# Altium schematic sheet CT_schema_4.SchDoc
size 310 x 177 mm
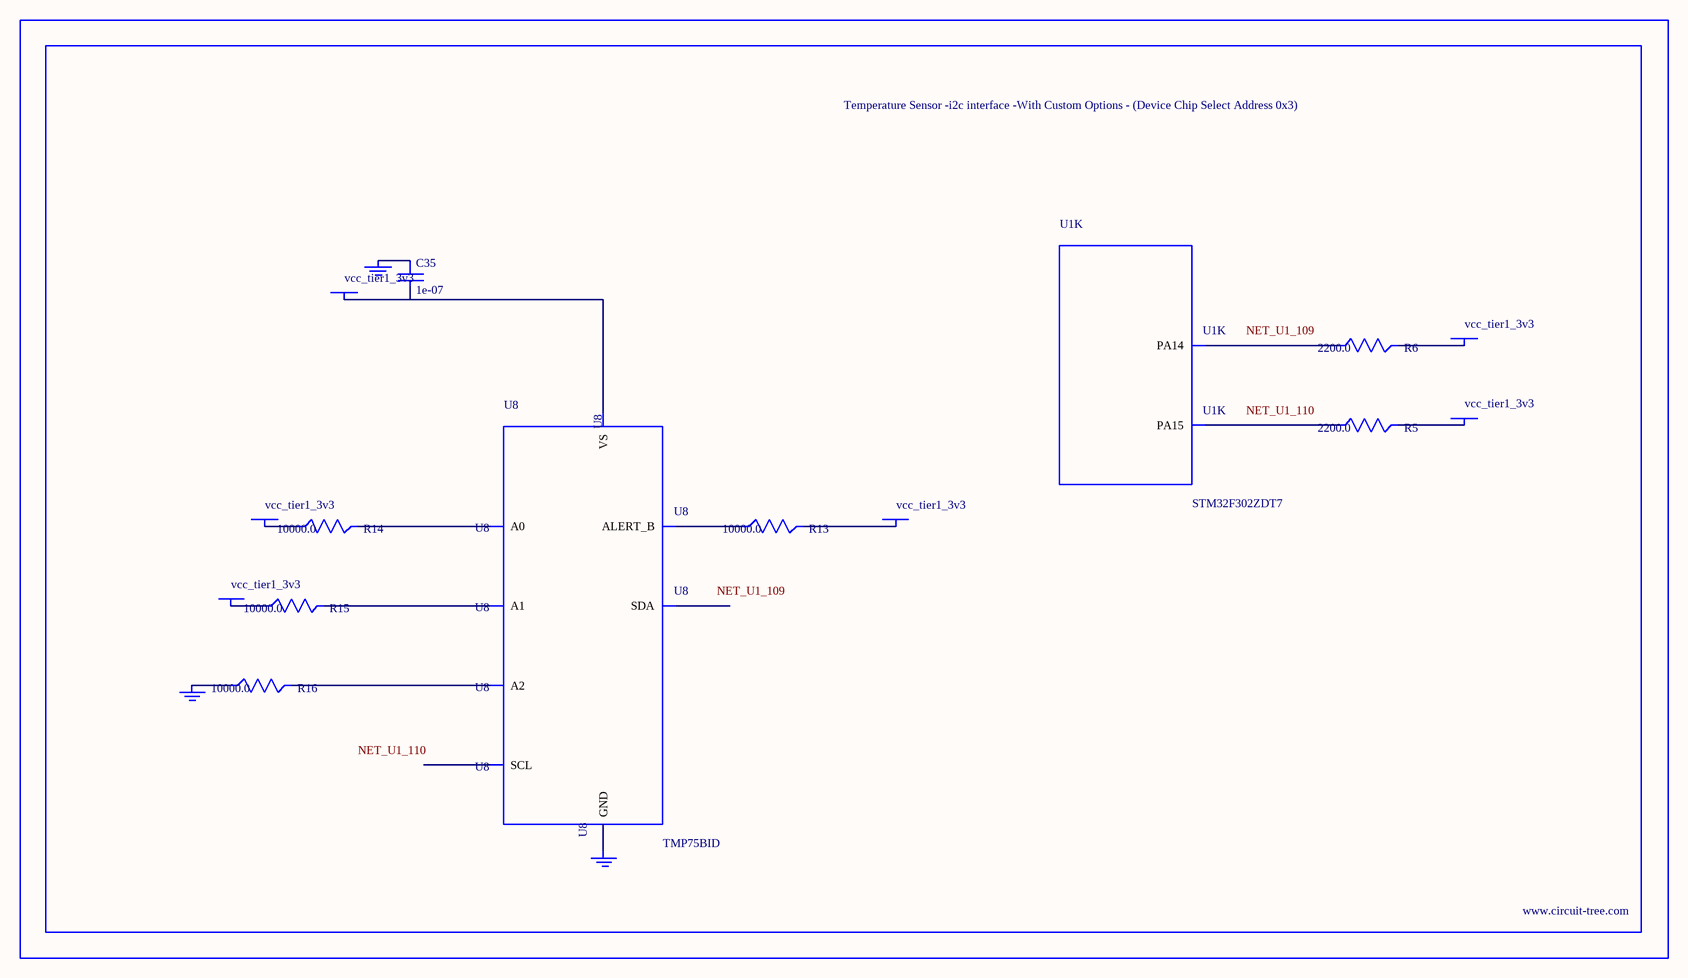
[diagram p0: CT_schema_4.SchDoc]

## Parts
BORDER3  (no value)
C35  1e-07  [C0402]
GND_INSTANCE_3_0  (no value)
GND_INSTANCE_3_1  (no value)
GND_INSTANCE_3_2  (no value)
POWER_INSTANCE_3_0  vcc_tier1_3v3
POWER_INSTANCE_3_1  vcc_tier1_3v3
POWER_INSTANCE_3_2  vcc_tier1_3v3
POWER_INSTANCE_3_3  vcc_tier1_3v3
POWER_INSTANCE_3_4  vcc_tier1_3v3
POWER_INSTANCE_3_5  vcc_tier1_3v3
R5  2200.0  [R0603]
R6  2200.0  [R0603]
R13  10000.0  [R0603]
R14  10000.0  [R0603]
R15  10000.0  [R0603]
R16  10000.0  [R0603]
U1  STM32F302ZDT7  [LQFP144]  (part K of 12)
U8  TMP75BID  [SOIC-8]

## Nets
NetC35_1: C35.1 GND_INSTANCE_3_1.0(GND)
NetC35_2: C35.2 POWER_INSTANCE_3_3.0(PWR) U8.8(VS)
NetGND_INSTANCE_3_0_0: GND_INSTANCE_3_0.0(GND) R16.1
NetGND_INSTANCE_3_2_0: GND_INSTANCE_3_2.0(GND) U8.4(GND)
NetPOWER_INSTANCE_3_0_0: POWER_INSTANCE_3_0.0(PWR) R13.2
NetPOWER_INSTANCE_3_1_0: POWER_INSTANCE_3_1.0(PWR) R15.1
NetPOWER_INSTANCE_3_2_0: POWER_INSTANCE_3_2.0(PWR) R14.1
NetPOWER_INSTANCE_3_4_0: POWER_INSTANCE_3_4.0(PWR) R6.2
NetPOWER_INSTANCE_3_5_0: POWER_INSTANCE_3_5.0(PWR) R5.2
NetR5_1: R5.1 U1.110(PA15)
NetR6_1: R6.1 U1.109(PA14)
NetR13_1: R13.1 U8.3(ALERT_B)
NetR14_2: R14.2 U8.7(A0)
NetR15_2: R15.2 U8.6(A1)
NetR16_2: R16.2 U8.5(A2)

Not connected (* = marked no-connect by the designer): U8 1(SDA) 2(SCL)

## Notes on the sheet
- Labels drawn without touching a wire or pin: NET_U1_109, NET_U1_110

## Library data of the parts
BORDER3 = BORDER_PAGE3
C35 = C0402C104K3RACTU
GND_INSTANCE_3_0-GND_INSTANCE_3_2 = GND
POWER_INSTANCE_3_0-POWER_INSTANCE_3_5 = PWR
R5 R6 = RC0603JR-072K2L
R13-R16 = RC0603JR-0710KL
